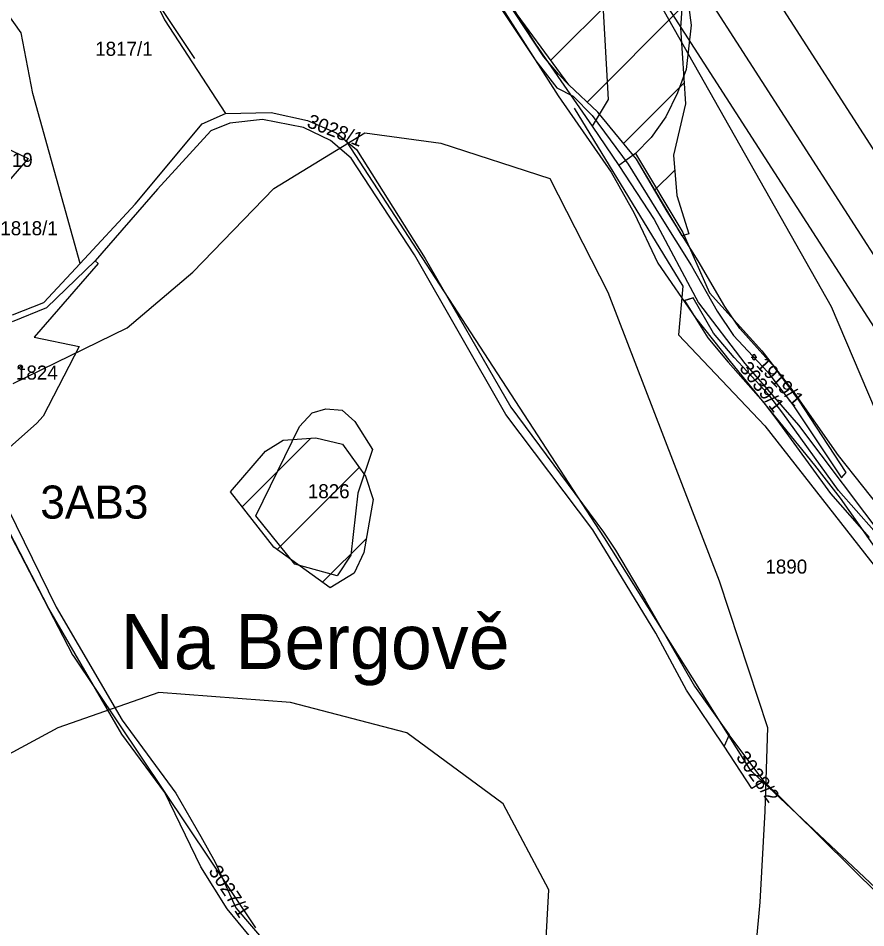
# Model space of a CAD drawing. Extents: x -564810 to -550519, y -1045831 to -1034011.
# Drawn here: x -553619.6 to -553312, y -1037726 to -1037395.7 of the extents above; entities that cross this region are included whole.
import ezdxf

# ---------------------------------------------------------------- set-up
doc = ezdxf.new("R2010")
doc.units = 0
for name, color, linetype in [('Interakční prvky', 7, 'Continuous'), ('KN stav', 7, 'Continuous'), ('Lesní porost', 7, 'Continuous'), ('Parcelní čísla', 7, 'Continuous'), ('Plynovod', 7, 'Continuous'), ('Polní cesty stavající', 7, 'Continuous'), ('přeložka st silnice', 7, 'Continuous'), ('STG', 7, 'Continuous'), ('Vrstva 4', 7, 'Continuous'), ('zamokř ploch', 7, 'Continuous')]:
    doc.layers.add(name, color=color, linetype=linetype)

msp = doc.modelspace()

# ---------------------------------------------------------------- linework, layer by layer
at = {"layer": 'Interakční prvky'}
for p, q in [((-553581.19, -1037371.9), (-553555.67, -1037410.32)), ((-553406.82, -1037584.39), (-553500.44, -1037440.34)), ((-553624.14, -1037580.18), (-553599.89, -1037626.92)), ((-553353.55, -1037669.06), (-553406.81, -1037584.4)), ((-553599.84, -1037627.02), (-553533.51, -1037725.95)), ((-553294.83, -1037724.3), (-553353.39, -1037669.26))]:
    msp.add_line(p, q, dxfattribs=at)
msp.add_lwpolyline([(-553417.87, -1037428.45), (-553378.32, -1037493.02), (-553379.9, -1037510.75), (-553348.58, -1037543.67), (-553272.8, -1037640.62), (-553222.18, -1037692.85), (-553203.51, -1037698.23), (-553185.48, -1037722.92)], dxfattribs=at)
for centre, start, end in [((-553407.66, -1037584.94), 32.1732, 33.0201), ((-553599, -1037626.46), 207.418, 213.8359), ((-553352.71, -1037668.53), 212.1732, 226.7768), ((-553534.34, -1037726.51), 31.8702, 33.8359)]:
    msp.add_arc(centre, 1, start, end, dxfattribs=at)
at = {"layer": 'KN stav'}
for p, q in [((-553585.89, -1037356.77), (-553566.55, -1037396.3)), ((-553443.11, -1037387.25), (-553431.8, -1037405.16)), ((-553618.57, -1037401.04), (-553625.95, -1037390.62)), ((-553444.77, -1037390.79), (-553423.65, -1037423.93)), ((-553376.18, -1037391.9), (-553375.36, -1037398.25)), ((-553566.55, -1037396.3), (-553544.36, -1037430.28)), ((-553375.36, -1037398.25), (-553377.14, -1037414.3)), ((-553614.31, -1037423.05), (-553618.57, -1037401.04)), ((-553431.8, -1037405.16), (-553411.25, -1037434.94)), ((-553377.14, -1037414.3), (-553380.27, -1037422.83)), ((-553597.09, -1037484.75), (-553614.31, -1037423.05)), ((-553423.65, -1037423.93), (-553404.38, -1037451.66)), ((-553380.27, -1037422.83), (-553384.57, -1037431.49)), ((-553552.87, -1037434.11), (-553544.36, -1037430.28)), ((-553544.36, -1037430.28), (-553527.8, -1037429.96)), ((-553527.8, -1037429.96), (-553514.57, -1037432.85)), ((-553384.57, -1037431.49), (-553389.87, -1037439.09)), ((-553577.12, -1037463.26), (-553552.87, -1037434.11)), ((-553542.79, -1037433.86), (-553549.73, -1037436.61)), ((-553530.89, -1037432.5), (-553542.79, -1037433.86)), ((-553516, -1037435.47), (-553530.89, -1037432.5)), ((-553514.57, -1037432.85), (-553504.23, -1037437.33)), ((-553549.73, -1037436.61), (-553569.01, -1037457.78)), ((-553506.26, -1037440.16), (-553516, -1037435.47)), ((-553504.23, -1037437.33), (-553496.86, -1037443.34)), ((-553411.25, -1037434.94), (-553401.6, -1037449.25)), ((-553629.95, -1037440.07), (-553615.96, -1037446.68)), ((-553498.81, -1037446.52), (-553506.26, -1037440.16)), ((-553389.87, -1037439.09), (-553395.53, -1037444.82)), ((-553496.86, -1037443.34), (-553471.95, -1037483.01)), ((-553395.53, -1037444.82), (-553401.6, -1037449.25)), ((-553395.53, -1037444.82), (-553378.43, -1037473.56)), ((-553615.96, -1037446.68), (-553628.05, -1037460.49)), ((-553475.79, -1037481.64), (-553498.81, -1037446.52)), ((-553401.6, -1037449.25), (-553388.79, -1037468.85)), ((-553404.38, -1037451.66), (-553396.01, -1037466.5)), ((-553569.01, -1037457.78), (-553591.67, -1037483.87)), ((-553597.09, -1037484.75), (-553577.12, -1037463.26)), ((-553396.01, -1037466.5), (-553387.48, -1037484.72)), ((-553388.79, -1037468.85), (-553372.64, -1037499.04)), ((-553378.43, -1037473.56), (-553368.69, -1037495.49)), ((-553591.67, -1037483.87), (-553609.38, -1037500.94)), ((-553591.67, -1037483.87), (-553590.59, -1037484.81)), ((-553442.63, -1037539.56), (-553475.79, -1037481.64)), ((-553471.95, -1037483.01), (-553440.76, -1037536.95)), ((-553590.59, -1037484.81), (-553613.8, -1037511.55)), ((-553610.27, -1037498.94), (-553597.09, -1037484.75)), ((-553387.48, -1037484.72), (-553373.74, -1037504.46)), ((-553368.69, -1037495.49), (-553349.69, -1037516.52)), ((-553609.38, -1037500.94), (-553621.77, -1037505.92)), ((-553621.67, -1037503.46), (-553610.27, -1037498.94)), ((-553372.64, -1037499.04), (-553355.89, -1037521.09)), ((-553373.74, -1037504.46), (-553361.21, -1037520.32)), ((-553613.8, -1037511.55), (-553597.47, -1037514.89)), ((-553597.47, -1037514.89), (-553610.52, -1037540.24)), ((-553349.69, -1037516.52), (-553338.46, -1037531.07)), ((-553361.21, -1037520.32), (-553330.63, -1037557.96)), ((-553355.89, -1037521.09), (-553336.4, -1037543.51)), ((-553338.46, -1037531.07), (-553322.04, -1037554.53)), ((-553440.76, -1037536.95), (-553407.12, -1037582.34)), ((-553610.52, -1037540.24), (-553612.9, -1037542.81)), ((-553517.47, -1037543.96), (-553512.97, -1037539)), ((-553512.97, -1037539), (-553507.93, -1037537.58)), ((-553507.93, -1037537.58), (-553502, -1037538.1)), ((-553502, -1037538.1), (-553497.42, -1037542.16)), ((-553411.1, -1037581.53), (-553442.63, -1037539.56)), ((-553612.9, -1037542.81), (-553628.96, -1037556.99)), ((-553497.42, -1037542.16), (-553490.97, -1037552.3)), ((-553336.4, -1037543.51), (-553301.26, -1037590.23)), ((-553533.31, -1037576.45), (-553517.47, -1037543.96)), ((-553490.97, -1037552.3), (-553496.3, -1037568.16)), ((-553322.04, -1037554.53), (-553303.87, -1037577.45)), ((-553330.63, -1037557.96), (-553321.23, -1037569.96)), ((-553608.46, -1037610.07), (-553631.51, -1037565.44)), ((-553626.19, -1037568.11), (-553605.82, -1037609.52)), ((-553496.3, -1037568.16), (-553498.84, -1037590.65)), ((-553321.23, -1037569.96), (-553304.75, -1037593.57)), ((-553519.26, -1037593.96), (-553533.31, -1037576.45)), ((-553388.12, -1037618.95), (-553411.1, -1037581.53)), ((-553407.12, -1037582.34), (-553402.79, -1037588.91)), ((-553402.79, -1037588.91), (-553392.01, -1037607.01)), ((-553498.84, -1037590.65), (-553503.8, -1037598.24)), ((-553503.8, -1037598.24), (-553519.26, -1037593.96)), ((-553605.82, -1037609.52), (-553581.88, -1037650.61)), ((-553392.01, -1037607.01), (-553374.17, -1037638.26)), ((-553581.99, -1037655.65), (-553608.46, -1037610.07)), ((-553377.07, -1037639.69), (-553388.12, -1037618.95)), ((-553374.17, -1037638.26), (-553361.6, -1037655.89)), ((-553363.41, -1037660.01), (-553377.07, -1037639.69)), ((-553581.88, -1037650.61), (-553562.43, -1037677.08)), ((-553566.43, -1037676.82), (-553581.99, -1037655.65)), ((-553361.6, -1037655.89), (-553363.41, -1037660.01)), ((-553348.97, -1037672.71), (-553361.6, -1037655.89)), ((-553353.38, -1037675.46), (-553363.41, -1037660.01)), ((-553348.97, -1037672.71), (-553353.38, -1037675.46)), ((-553306.96, -1037714.28), (-553348.97, -1037672.71)), ((-553553.34, -1037703.85), (-553566.43, -1037676.82)), ((-553562.43, -1037677.08), (-553553.28, -1037692.86)), ((-553553.28, -1037692.86), (-553548.17, -1037702.12)), ((-553548.17, -1037702.12), (-553540.56, -1037718.68)), ((-553543.71, -1037719.15), (-553553.34, -1037703.85)), ((-553540.56, -1037718.68), (-553529.3, -1037732.04)), ((-553528.2, -1037737.83), (-553543.71, -1037719.15))]:
    msp.add_line(p, q, dxfattribs=at)
at = {"layer": 'Lesní porost'}
for p, q in [((-553426.3, -1037411.02), (-553379.87, -1037364.59)), ((-553413.15, -1037426.16), (-553378.74, -1037391.75)), ((-553399.9, -1037441.19), (-553377.89, -1037419.17)), ((-553388.53, -1037458.1), (-553381.3, -1037450.88)), ((-553538.31, -1037573.1), (-553513.38, -1037548.17)), ((-553525.56, -1037588.64), (-553495.81, -1037558.89)), ((-553509.18, -1037600.54), (-553493.23, -1037584.59))]:
    msp.add_line(p, q, dxfattribs=at)
for points in [[(-553460.54, -1037364.54), (-553460.18, -1037359.15), (-553457.63, -1037354.64), (-553452.02, -1037351.71), (-553431.19, -1037349.7), (-553412.13, -1037332.28), (-553401.64, -1037334.03), (-553387.72, -1037348.7), (-553380.58, -1037361.53), (-553377.58, -1037374.37), (-553379.24, -1037399.22), (-553377.37, -1037426.76), (-553381.74, -1037445.49), (-553380.56, -1037460.1), (-553376.21, -1037473.97), (-553378.62, -1037474.73), (-553395.18, -1037446.95), (-553409.18, -1037429.87), (-553419.77, -1037419.98), (-553442.82, -1037388.35), (-553458.61, -1037364.88), (-553460.3, -1037362.37)], [(-553542.57, -1037567.67), (-553529.87, -1037552.96), (-553523.4, -1037548.95), (-553511.56, -1037548.03), (-553501.88, -1037550.43), (-553493.59, -1037561.99), (-553490.74, -1037570.42), (-553494.12, -1037589.66), (-553497.66, -1037597.24), (-553506.39, -1037602.56), (-553526.82, -1037587.73)]]:
    msp.add_lwpolyline(points, close=True, dxfattribs=at)
at = {"layer": 'Plynovod'}
for points in [[(-554428.56, -1035578.55), (-554428.56, -1035578.55), (-554428.56, -1035578.55), (-554027.79, -1036081.22), (-553723.76, -1036467.01), (-553550.38, -1036705.78), (-553550.38, -1036705.78), (-553522.74, -1037110.43), (-553438.57, -1037242.38), (-553213.69, -1037591.73), (-553193.58, -1037703.57), (-553145.84, -1037777.72), (-553110.67, -1037838.04), (-552972.47, -1038070.52), (-552972.47, -1038070.52), (-552302.85, -1038878.56)], [(-552322.24, -1038886.46), (-552991.86, -1038078.43), (-553130.06, -1037845.94), (-553165.24, -1037785.62), (-553212.98, -1037711.48), (-553233.08, -1037599.64), (-553457.96, -1037250.28), (-553542.14, -1037118.33), (-553569.78, -1036713.69), (-553743.15, -1036474.92), (-554047.18, -1036089.12), (-554447.95, -1035586.45)], [(-552330.5, -1038899.71), (-553000.12, -1038091.67), (-553138.32, -1037859.19), (-553173.5, -1037798.87), (-553221.24, -1037724.72), (-553241.34, -1037612.88), (-553466.22, -1037263.53), (-553550.4, -1037131.58), (-553578.03, -1036726.93), (-553751.41, -1036488.16), (-554055.44, -1036102.37), (-554456.21, -1035599.7)]]:
    msp.add_lwpolyline(points, dxfattribs=at)
at = {"layer": 'Polní cesty stavající'}
for p, q in [((-553428.82, -1037409.71), (-553442.82, -1037388.35)), ((-553445.57, -1037390.46), (-553431.74, -1037411.21)), ((-553431.74, -1037411.21), (-553424.09, -1037421.07)), ((-553423.56, -1037416.1), (-553428.82, -1037409.71)), ((-553419.77, -1037419.98), (-553423.56, -1037416.1)), ((-553424.09, -1037421.07), (-553418.14, -1037424.01)), ((-553409.18, -1037429.87), (-553419.77, -1037419.98)), ((-553418.14, -1037424.01), (-553411.29, -1037431.05)), ((-553411.29, -1037431.05), (-553398.21, -1037448.76)), ((-553395.18, -1037446.95), (-553409.18, -1037429.87)), ((-553384.12, -1037465.97), (-553395.18, -1037446.95)), ((-553398.21, -1037448.76), (-553386.64, -1037467.45)), ((-553386.64, -1037467.45), (-553375.22, -1037485.63)), ((-553372.78, -1037483.79), (-553384.12, -1037465.97)), ((-553363.08, -1037500.35), (-553372.78, -1037483.79)), ((-553375.22, -1037485.63), (-553365.94, -1037502.04)), ((-553377.79, -1037498.27), (-553374.58, -1037497.24)), ((-553374.58, -1037497.24), (-553377.79, -1037498.27)), ((-553367.25, -1037510.11), (-553374.58, -1037497.24)), ((-553377.79, -1037498.27), (-553369.31, -1037511.81)), ((-553357.71, -1037508.36), (-553363.08, -1037500.35)), ((-553365.94, -1037502.04), (-553359.93, -1037510.95)), ((-553359.74, -1037518.87), (-553367.25, -1037510.11)), ((-553345.12, -1037522.45), (-553357.71, -1037508.36)), ((-553369.31, -1037511.81), (-553361.92, -1037520.59)), ((-553359.93, -1037510.95), (-553347.59, -1037524.15)), ((-553361.92, -1037520.59), (-553349.18, -1037534.98)), ((-553347.15, -1037532.52), (-553359.74, -1037518.87)), ((-553336.26, -1037534.47), (-553345.12, -1037522.45)), ((-553347.59, -1037524.15), (-553338.49, -1037536.07)), ((-553342.06, -1037539.14), (-553347.15, -1037532.52)), ((-553349.18, -1037534.98), (-553344.26, -1037541.52)), ((-553338.49, -1037536.07), (-553320.74, -1037562.6)), ((-553319.06, -1037560.67), (-553336.26, -1037534.47)), ((-553321.89, -1037567.23), (-553342.06, -1037539.14)), ((-553344.26, -1037541.52), (-553324.74, -1037568.32)), ((-553320.74, -1037562.6), (-553319.06, -1037560.67)), ((-553324.74, -1037568.32), (-553310.75, -1037584.32)), ((-553309.06, -1037581.77), (-553321.89, -1037567.23))]:
    msp.add_line(p, q, dxfattribs=at)
at = {"layer": 'přeložka st silnice'}
msp.add_lwpolyline([(-552359.45, -1038509.27), (-552838.68, -1038201.82), (-552981.64, -1038092.23), (-553086.65, -1037975.23), (-553204.95, -1037781.11), (-553324.39, -1037500.52), (-553448.24, -1037281.74), (-553591.55, -1037076.57), (-553686.12, -1036910.24), (-553749.25, -1036695.02), (-553795.26, -1036480.46), (-553954.63, -1036164.34)], dxfattribs=at)
at = {"layer": 'STG'}
for points in [[(-553621.42, -1037528.33), (-553580.09, -1037508.12), (-553556.21, -1037487.9), (-553526.81, -1037457.58), (-553493.74, -1037437.37), (-553466.19, -1037441.04), (-553426.69, -1037453.91), (-553405.56, -1037495.25), (-553365.15, -1037599.99), (-553347.69, -1037653.28), (-553348.61, -1037683.61), (-553350.45, -1037716.68), (-553353.21, -1037747)], [(-553527.73, -1038019.88), (-553522.59, -1037969.44), (-553504.22, -1037932.69), (-553480.33, -1037890.43), (-553461.96, -1037844.49), (-553439.92, -1037782.01), (-553428.89, -1037745.26), (-553427.06, -1037712.18), (-553443.59, -1037680.94), (-553478.5, -1037655.21), (-553520.75, -1037644.19), (-553568.51, -1037640.51), (-553605.26, -1037653.38), (-553653.02, -1037679.1)]]:
    msp.add_lwpolyline(points, dxfattribs=at)
at = {"layer": 'Vrstva 4'}
for p, q in [((-553407.5, -1037388.51), (-553405.52, -1037425.26)), ((-553405.52, -1037425.26), (-553411.25, -1037434.94))]:
    msp.add_line(p, q, dxfattribs=at)
at = {"layer": 'zamokř ploch'}
for p, q in [((-553353.54, -1037518.78), (-553351.54, -1037518.78)), ((-553353.04, -1037518.28), (-553353.04, -1037519.28)), ((-553352.04, -1037518.28), (-553352.04, -1037519.28)), ((-553618.82, -1037523.12), (-553617.22, -1037523.12))]:
    msp.add_line(p, q, dxfattribs=at)
msp.add_circle((-553618.82, -1037522.37), 0.75, dxfattribs=at)
for centre, start, end in [((-553352.54, -1037518.28), 0, 180), ((-553352.54, -1037519.28), 180, 0)]:
    msp.add_arc(centre, 0.5, start, end, dxfattribs=at)

# ---------------------------------------------------------------- texts
at = {"layer": 'Parcelní čísla'}
for s, height, p in [('1817/1', 5.1, (-553591.67, -1037409.38)), ('1819', 5.1, (-553629.5, -1037449.74)), ('1818/1', 5.1, (-553626.1, -1037474.53)), ('1824', 5.1, (-553620.42, -1037526.95)), ('1826', 5.1, (-553514.49, -1037570.02)), ('1890', 5.1, (-553348.41, -1037597.39)), ('Na Bergově', 20, (-553582.46, -1037632.07))]:
    msp.add_text(s, height=height, dxfattribs=at).set_placement(p)
for s, rotation, p in [('3028/1', 339.3434, (-553515.16, -1037435.13)), ('3039/1', 308.0976, (-553358.11, -1037522.87)), ('1919/1', 313.3374, (-553352.02, -1037521.85)), ('3028/2', 305.6996, (-553359.27, -1037664.08)), ('3027/1', 303.332, (-553550.73, -1037705.38))]:
    msp.add_text(s, height=5.1, rotation=rotation, dxfattribs=at).set_placement(p)
at = {"layer": 'STG'}
msp.add_text('3AB3', height=12, dxfattribs=at).set_placement((-553611.59, -1037577.41))

doc.saveas('drawing.dxf')
